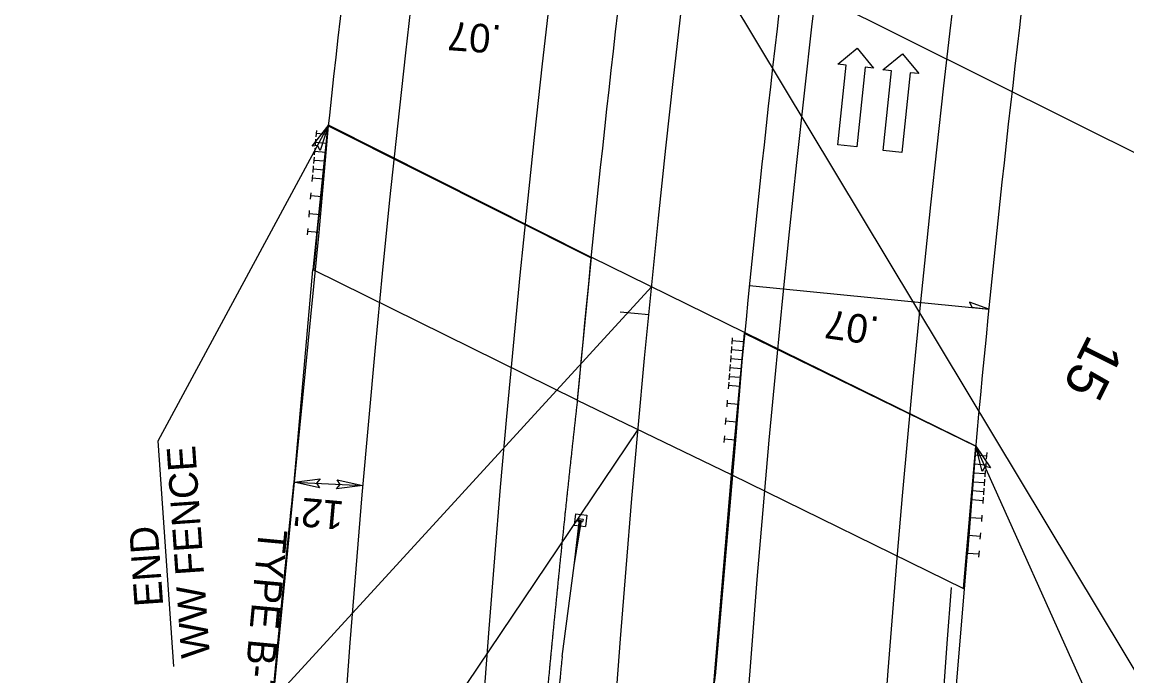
# Model space of a CAD drawing. Extents: x 2389099 to 2405615, y 552200 to 573532.
# Drawn here: x 2400056 to 2400248.8, y 568252.4 to 568366.6 of the extents above; entities that cross this region are included whole.
import ezdxf

# ---------------------------------------------------------------- set-up
doc = ezdxf.new("R2010")
doc.units = 0
for name, color, linetype in [('Prop Approach Slab', 7, 'Continuous'), ('Prop Approach Slab Hatching', 7, 'Continuous'), ('Prop Cable Guiderail Single Face', 7, 'Continuous'), ('Prop Conc Expressway Gutter', 7, 'Continuous'), ('Prop Dimension', 7, 'Continuous'), ('Prop Dimension Text', 7, 'Continuous'), ('Prop DSN Text', 7, 'Continuous'), ('Prop EOT', 7, 'Continuous'), ('Prop Guardrail', 7, 'Continuous'), ('Prop Horizontal Alignment', 7, 'Continuous'), ('Prop Horizontal Alignment Curve and Spiral Data', 7, 'Continuous'), ('Prop Horizontal Alignment Tick Small', 7, 'Continuous'), ('Prop Lane Arrow Through CELL', 7, 'Continuous'), ('Prop SAU III Approach CELL', 7, 'Continuous'), ('Prop Super Arrow 1 Lane CELL', 7, 'Continuous'), ('Prop Superelevation Label', 7, 'Continuous')]:
    doc.layers.add(name, color=color, linetype=linetype)

msp = doc.modelspace()

# ---------------------------------------------------------------- linework, layer by layer
at = {"layer": 'Prop Approach Slab'}
for p, q in [((2400109.42, 568348.51), (2400155.33, 568325.42)), ((2400182.02, 568312.3), (2400222.45, 568292.56))]:
    msp.add_line(p, q, dxfattribs=at)
for radius, start, end in [(2959, 170.18806, 174.3984), (2911, 170.46446, 174.75565), (2883, 170.63278, 174.96393), (2841, 170.90765, 175.29183)]:
    msp.add_arc((2403051.7, 568034.46), radius, start, end, dxfattribs=at)
at = {"layer": 'Prop Approach Slab Hatching'}
for points in [[(2400109.38, 568348.65), (2400155.29, 568325.55), (2400152.89, 568300.54), (2400106.79, 568323.31)], [(2400182.02, 568312.3), (2400179.74, 568287.59), (2400220.29, 568267.65), (2400222.45, 568292.56)]]:
    msp.add_lwpolyline(points, close=True, dxfattribs=at)
at = {"layer": 'Prop Cable Guiderail Single Face'}
msp.add_spline([(2400150.24, 568255.82), (2400150.2, 568255.35), (2400150.11, 568254.45), (2400150.02, 568253.55), (2400149.94, 568252.65), (2400149.85, 568251.75), (2400149.77, 568250.85), (2400149.68, 568249.95), (2400149.6, 568249.05), (2400149.51, 568248.15), (2400149.43, 568247.25), (2400149.35, 568246.35), (2400149.26, 568245.46), (2400149.18, 568244.55), (2400149.1, 568243.65), (2400149.01, 568242.75), (2400148.93, 568241.85), (2400148.85, 568240.95), (2400148.77, 568240.05), (2400148.68, 568239.15), (2400148.6, 568238.25), (2400148.52, 568237.35), (2400148.44, 568236.45), (2400148.36, 568235.55), (2400148.28, 568234.64), (2400148.2, 568233.74)], degree=3, dxfattribs=at)
at = {"layer": 'Prop Conc Expressway Gutter'}
msp.add_lwpolyline([(2400216.81, 568249.06), (2400217.48, 568258.06), (2400218.24, 568267.82)], dxfattribs=at)
at = {"layer": 'Prop Dimension'}
for p, q in [((2400222.45, 568292.56), (2400155.29, 568325.55)), ((2400165.83, 568320.38), (2400033.57, 568175.96)), ((2400152.89, 568300.54), (2400179.74, 568287.59)), ((2400163.47, 568295.43), (2400065.62, 568150.18)), ((2400103.44, 568286.25), (2400115.43, 568285.64))]:
    msp.add_line(p, q, dxfattribs=at)
for points in [[(2400106.6, 568344.92), (2400109.42, 568348.51), (2400107.97, 568344.15), (2400107.54, 568345.04)], [(2400223.59, 568288.14), (2400222.45, 568292.56), (2400225.04, 568288.76), (2400224.07, 568288.96)], [(2400107.89, 568285.24), (2400103.44, 568286.25), (2400108, 568286.82), (2400107.38, 568286.05)], [(2400110.97, 568286.64), (2400115.43, 568285.64), (2400110.87, 568285.07), (2400111.48, 568285.84)]]:
    msp.add_lwpolyline(points, close=True, dxfattribs=at)
at = {"layer": 'Prop DSN Text'}
for p, q in [((2400079.7, 568293.44), (2400109.42, 568348.51)), ((2400082.45, 568254.06), (2400079.7, 568293.44)), ((2400243.18, 568246.41), (2400222.45, 568292.56)), ((2400152.58, 568280.73), (2400152.32, 568278.75)), ((2400152.58, 568280.73), (2400154.56, 568280.47)), ((2400154.56, 568280.47), (2400154.3, 568278.49)), ((2400152.32, 568278.75), (2400154.3, 568278.49)), ((2400152.37, 568271.68), (2400153.25, 568279.64)), ((2400152.37, 568271.68), (2400153.44, 568279.61)), ((2400152.37, 568271.68), (2400153.64, 568279.56)), ((2400153.06, 568279.91), (2400152.99, 568279.42)), ((2400152.99, 568279.42), (2400153.82, 568279.31)), ((2400153.06, 568279.91), (2400153.89, 568279.8)), ((2400153.89, 568279.8), (2400153.82, 568279.31)), ((2400150.24, 568255.82), (2400152.37, 568271.68)), ((2400152.37, 568271.68), (2400152.37, 568271.68))]:
    msp.add_line(p, q, dxfattribs=at)
at = {"layer": 'Prop EOT'}
for p, q in [((2400103.44, 568286.25), (2400106.72, 568323.35)), ((2400176.75, 568251.01), (2400179.81, 568287.55))]:
    msp.add_line(p, q, dxfattribs=at)
for radius, start in [(2923, 119.41161), (2877, 119.41161), (2947, 148.75529), (2853, 154.68245)]:
    msp.add_arc((2403051.7, 568034.46), radius, start, 180.94658, dxfattribs=at)
for points in [[(2400152.89, 568300.53), (2400152.79, 568299.63), (2400152.69, 568298.74), (2400152.59, 568297.84), (2400152.49, 568296.94), (2400152.39, 568296.04), (2400152.29, 568295.13), (2400152.19, 568294.24), (2400152.09, 568293.34), (2400151.99, 568292.44), (2400151.9, 568291.54), (2400151.8, 568290.64), (2400151.7, 568289.74), (2400151.6, 568288.85), (2400151.51, 568287.95), (2400151.41, 568287.05), (2400151.31, 568286.15), (2400151.22, 568285.24), (2400151.12, 568284.34), (2400151.03, 568283.44), (2400150.93, 568282.55), (2400150.84, 568281.65), (2400150.74, 568280.75), (2400150.65, 568279.85), (2400150.55, 568278.95), (2400150.46, 568278.05), (2400150.37, 568277.15), (2400150.27, 568276.25), (2400150.18, 568275.34), (2400150.09, 568274.45), (2400150, 568273.55), (2400149.9, 568272.65), (2400149.81, 568271.75), (2400149.72, 568270.85), (2400149.63, 568269.95), (2400149.54, 568269.05), (2400149.45, 568268.15), (2400149.36, 568267.25), (2400149.27, 568266.35), (2400149.18, 568265.44), (2400149.09, 568264.54), (2400149, 568263.64), (2400148.91, 568262.75), (2400148.82, 568261.85), (2400148.73, 568260.95), (2400148.64, 568260.05), (2400148.56, 568259.15), (2400148.47, 568258.25), (2400148.38, 568257.35), (2400148.29, 568256.45), (2400148.21, 568255.54), (2400148.12, 568254.64), (2400148.03, 568253.74), (2400147.95, 568252.84), (2400147.86, 568251.94), (2400147.78, 568251.04), (2400147.69, 568250.14), (2400147.61, 568249.24), (2400147.52, 568248.34), (2400147.44, 568247.44), (2400147.35, 568246.54), (2400147.27, 568245.64), (2400147.19, 568244.73), (2400147.1, 568243.83), (2400147.02, 568242.93), (2400146.94, 568242.03), (2400146.86, 568241.13), (2400146.77, 568240.23), (2400146.69, 568239.33), (2400146.61, 568238.43), (2400146.53, 568237.53), (2400146.45, 568236.63), (2400146.37, 568235.73), (2400146.29, 568234.82), (2400146.21, 568233.92)], [(2400098.53, 568235.45), (2400098.6, 568236.14), (2400098.66, 568236.82), (2400098.72, 568237.51), (2400098.78, 568238.2), (2400098.84, 568238.89), (2400098.9, 568239.57), (2400098.96, 568240.26), (2400099.02, 568240.95), (2400099.08, 568241.63), (2400099.15, 568242.32), (2400099.21, 568243), (2400099.27, 568243.7), (2400099.33, 568244.38), (2400099.39, 568245.07), (2400099.46, 568245.76), (2400099.52, 568246.44), (2400099.58, 568247.13), (2400099.65, 568247.81), (2400099.71, 568248.5), (2400099.77, 568249.19), (2400099.84, 568249.88), (2400099.9, 568250.56), (2400099.96, 568251.25), (2400100.03, 568251.94), (2400100.09, 568252.62), (2400100.16, 568253.31), (2400100.22, 568253.99), (2400100.29, 568254.68), (2400100.35, 568255.36), (2400100.42, 568256.06), (2400100.48, 568256.75), (2400100.55, 568257.43), (2400100.61, 568258.12), (2400100.68, 568258.8), (2400100.74, 568259.49), (2400100.81, 568260.17), (2400100.88, 568260.86), (2400100.94, 568261.55), (2400101.01, 568262.23), (2400101.08, 568262.92), (2400101.14, 568263.6), (2400101.21, 568264.3), (2400101.28, 568264.98), (2400101.34, 568265.67), (2400101.41, 568266.36), (2400101.48, 568267.04), (2400101.55, 568267.73), (2400101.61, 568268.41), (2400101.68, 568269.1), (2400101.75, 568269.78), (2400101.82, 568270.47), (2400101.89, 568271.16), (2400101.96, 568271.84), (2400102.02, 568272.53), (2400102.09, 568273.21), (2400102.16, 568273.9), (2400102.23, 568274.58), (2400102.3, 568275.27), (2400102.37, 568275.95), (2400102.44, 568276.65), (2400102.51, 568277.34), (2400102.58, 568278.02), (2400102.65, 568278.71), (2400102.72, 568279.39), (2400102.79, 568280.08), (2400102.86, 568280.76), (2400102.93, 568281.45), (2400103.01, 568282.14), (2400103.08, 568282.82), (2400103.15, 568283.51), (2400103.22, 568284.19), (2400103.29, 568284.88), (2400103.44, 568286.25)], [(2400176.95, 568252.4), (2400176.85, 568251.71), (2400176.75, 568251.01), (2400176.65, 568250.32), (2400176.55, 568249.62), (2400176.46, 568248.93), (2400176.36, 568248.24), (2400176.26, 568247.54), (2400176.16, 568246.85), (2400176.06, 568246.16), (2400175.96, 568245.46), (2400175.87, 568244.77), (2400175.77, 568244.07), (2400175.67, 568243.38), (2400175.57, 568242.68), (2400175.48, 568241.98), (2400175.38, 568241.29), (2400175.28, 568240.59), (2400175.19, 568239.9), (2400175.09, 568239.21), (2400174.99, 568238.51), (2400174.9, 568237.82), (2400174.8, 568237.13), (2400174.7, 568236.43), (2400174.61, 568235.73), (2400174.51, 568235.03), (2400174.42, 568234.34), (2400174.32, 568233.65), (2400174.23, 568232.95), (2400174.13, 568232.26), (2400174.04, 568231.57), (2400173.94, 568230.87), (2400173.85, 568230.17), (2400173.75, 568229.47), (2400173.66, 568228.78), (2400173.57, 568228.09), (2400173.47, 568227.39), (2400173.38, 568226.7), (2400173.29, 568225.99), (2400173.19, 568225.3), (2400173.1, 568224.61), (2400173.01, 568223.91), (2400172.91, 568223.22), (2400172.82, 568222.53), (2400172.73, 568221.82), (2400172.64, 568221.13), (2400172.54, 568220.43), (2400172.45, 568219.74), (2400172.36, 568219.05), (2400172.27, 568218.34), (2400172.18, 568217.65), (2400172.09, 568216.95), (2400172, 568216.26), (2400171.9, 568215.57), (2400171.81, 568214.86), (2400171.72, 568214.17), (2400171.63, 568213.48), (2400171.54, 568212.78), (2400171.45, 568212.09), (2400171.36, 568211.38), (2400171.27, 568210.69), (2400171.18, 568210), (2400171.09, 568209.3), (2400171, 568208.6), (2400170.92, 568207.9), (2400170.83, 568207.21), (2400170.74, 568206.52), (2400170.65, 568205.81), (2400170.56, 568205.12), (2400170.47, 568204.43), (2400170.39, 568203.73), (2400170.3, 568203.03), (2400170.21, 568202.33), (2400170.12, 568201.64), (2400170.04, 568200.94)]]:
    msp.add_spline(points, degree=3, dxfattribs=at)
at = {"layer": 'Prop Guardrail'}
for p, q in [((2400107.77, 568329.84), (2400103.44, 568286.25)), ((2400180.52, 568293.61), (2400176.95, 568252.4)), ((2400103.44, 568286.25), (2400098.49, 568234.9)), ((2400218.6, 568244.99), (2400220.99, 568273.87))]:
    msp.add_line(p, q, dxfattribs=at)
msp.add_spline([(2400176.95, 568252.4), (2400176.85, 568251.71), (2400176.75, 568251.01), (2400176.65, 568250.32), (2400176.55, 568249.62), (2400176.46, 568248.93), (2400176.36, 568248.24), (2400176.26, 568247.54), (2400176.16, 568246.85), (2400176.06, 568246.16), (2400175.96, 568245.46), (2400175.87, 568244.77), (2400175.77, 568244.07), (2400175.67, 568243.38), (2400175.57, 568242.68), (2400175.48, 568241.98), (2400175.38, 568241.29), (2400175.28, 568240.59), (2400175.19, 568239.9), (2400175.09, 568239.21), (2400174.99, 568238.51), (2400174.9, 568237.82), (2400174.8, 568237.13), (2400174.7, 568236.43), (2400174.61, 568235.73), (2400174.51, 568235.03), (2400174.42, 568234.34), (2400174.32, 568233.65), (2400174.23, 568232.95), (2400174.13, 568232.26), (2400174.04, 568231.57), (2400173.94, 568230.87), (2400173.85, 568230.17), (2400173.75, 568229.47), (2400173.66, 568228.78), (2400173.57, 568228.09), (2400173.47, 568227.39), (2400173.38, 568226.7), (2400173.29, 568225.99), (2400173.19, 568225.3), (2400173.1, 568224.61), (2400173.01, 568223.91), (2400172.91, 568223.22), (2400172.82, 568222.53), (2400172.73, 568221.82), (2400172.64, 568221.13), (2400172.54, 568220.43), (2400172.45, 568219.74), (2400172.36, 568219.05), (2400172.27, 568218.34), (2400172.18, 568217.65), (2400172.09, 568216.95), (2400172, 568216.26), (2400171.9, 568215.57), (2400171.81, 568214.86), (2400171.72, 568214.17), (2400171.63, 568213.48), (2400171.54, 568212.78), (2400171.45, 568212.09), (2400171.36, 568211.38), (2400171.27, 568210.69), (2400171.18, 568210), (2400171.09, 568209.3), (2400171, 568208.6), (2400170.92, 568207.9), (2400170.83, 568207.21), (2400170.74, 568206.52), (2400170.65, 568205.81), (2400170.56, 568205.12), (2400170.47, 568204.43), (2400170.39, 568203.73), (2400170.3, 568203.03), (2400170.21, 568202.33), (2400170.12, 568201.64), (2400170.04, 568200.94)], degree=3, dxfattribs=at)
at = {"layer": 'Prop Horizontal Alignment'}
msp.add_line((2399810.95, 568562.89), (2400526.85, 568205.84), dxfattribs=at)
msp.add_arc((2403051.7, 568034.46), 2900, 119.41161, 180.94658, dxfattribs=at)
at = {"layer": 'Prop Horizontal Alignment Curve and Spiral Data'}
msp.add_line((2400352.63, 568082.83), (2400172.66, 568382.49), dxfattribs=at)
at = {"layer": 'Prop Horizontal Alignment Tick Small'}
msp.add_line((2400165.35, 568315.46), (2400160.37, 568315.94), dxfattribs=at)
at = {"layer": 'Prop Lane Arrow Through CELL'}
for p, q in [((2400198.35, 568359.23), (2400201.76, 568362.04)), ((2400201.76, 568362.04), (2400204.62, 568358.57)), ((2400206.25, 568358.26), (2400209.66, 568361.07)), ((2400209.66, 568361.07), (2400212.52, 568357.6)), ((2400199.84, 568359.07), (2400198.35, 568359.23)), ((2400198.39, 568345.15), (2400199.84, 568359.07)), ((2400203.12, 568358.73), (2400201.67, 568344.8)), ((2400204.62, 568358.57), (2400203.12, 568358.73)), ((2400207.74, 568358.1), (2400206.25, 568358.26)), ((2400206.29, 568344.18), (2400207.74, 568358.1)), ((2400211.03, 568357.76), (2400209.57, 568343.83)), ((2400212.52, 568357.6), (2400211.03, 568357.76)), ((2400201.67, 568344.8), (2400198.39, 568345.15)), ((2400209.57, 568343.83), (2400206.29, 568344.18))]:
    msp.add_line(p, q, dxfattribs=at)
at = {"layer": 'Prop SAU III Approach CELL'}
for p, q in [((2400109.42, 568348.51), (2400107.77, 568329.84)), ((2400107.2, 568346.15), (2400107.1, 568345.01)), ((2400107.34, 568347.7), (2400107.24, 568346.56)), ((2400109.28, 568346.96), (2400107.29, 568347.13)), ((2400107.06, 568344.59), (2400106.96, 568343.45)), ((2400109, 568343.84), (2400107.01, 568344.02)), ((2400109.14, 568345.4), (2400107.15, 568345.58)), ((2400106.92, 568343.03), (2400106.82, 568341.89)), ((2400108.87, 568342.29), (2400106.87, 568342.46)), ((2400106.79, 568341.48), (2400106.69, 568340.34)), ((2400108.73, 568340.73), (2400106.74, 568340.91)), ((2400106.65, 568339.92), (2400106.55, 568338.78)), ((2400108.59, 568339.17), (2400106.6, 568339.35)), ((2400106.37, 568336.81), (2400106.27, 568335.67)), ((2400108.32, 568336.06), (2400106.32, 568336.24)), ((2400106.1, 568333.7), (2400106, 568332.55)), ((2400108.04, 568332.95), (2400106.05, 568333.12)), ((2400105.82, 568330.58), (2400105.72, 568329.44)), ((2400107.77, 568329.84), (2400105.77, 568330.01)), ((2400179.95, 568311.48), (2400179.86, 568310.33)), ((2400182.02, 568312.3), (2400180.52, 568293.61)), ((2400179.82, 568309.92), (2400179.73, 568308.78)), ((2400181.77, 568309.19), (2400179.78, 568309.35)), ((2400181.9, 568310.74), (2400179.9, 568310.91)), ((2400179.7, 568308.36), (2400179.61, 568307.22)), ((2400181.65, 568307.63), (2400179.65, 568307.79)), ((2400179.57, 568306.8), (2400179.48, 568305.66)), ((2400181.52, 568306.07), (2400179.53, 568306.23)), ((2400179.32, 568303.69), (2400179.23, 568302.55)), ((2400179.45, 568305.25), (2400179.36, 568304.1)), ((2400181.4, 568304.51), (2400179.4, 568304.67)), ((2400181.27, 568302.96), (2400179.28, 568303.12)), ((2400179.07, 568300.57), (2400178.98, 568299.43)), ((2400181.02, 568299.84), (2400179.03, 568300)), ((2400178.82, 568297.46), (2400178.73, 568296.32)), ((2400180.77, 568296.73), (2400178.78, 568296.89)), ((2400178.57, 568294.34), (2400178.48, 568293.2)), ((2400180.52, 568293.61), (2400178.53, 568293.77)), ((2400222.45, 568292.56), (2400220.99, 568273.87)), ((2400222.33, 568291), (2400224.32, 568290.85)), ((2400224.37, 568291.42), (2400224.28, 568290.28)), ((2400222.21, 568289.45), (2400224.2, 568289.29)), ((2400224.12, 568288.3), (2400224.04, 568287.16)), ((2400224.25, 568289.86), (2400224.16, 568288.72)), ((2400221.96, 568286.33), (2400223.96, 568286.17)), ((2400222.09, 568287.89), (2400224.08, 568287.73)), ((2400224, 568286.75), (2400223.91, 568285.6)), ((2400221.84, 568284.77), (2400223.84, 568284.62)), ((2400223.88, 568285.19), (2400223.79, 568284.05)), ((2400221.72, 568283.21), (2400223.72, 568283.06)), ((2400223.76, 568283.63), (2400223.67, 568282.49)), ((2400223.52, 568280.51), (2400223.43, 568279.37)), ((2400221.48, 568280.1), (2400223.47, 568279.94)), ((2400221.23, 568276.98), (2400223.23, 568276.83)), ((2400223.27, 568277.4), (2400223.18, 568276.26)), ((2400220.99, 568273.87), (2400222.98, 568273.71)), ((2400223.03, 568274.28), (2400222.94, 568273.14))]:
    msp.add_line(p, q, dxfattribs=at)
at = {"layer": 'Prop Super Arrow 1 Lane CELL'}
msp.add_line((2400182.93, 568320.62), (2400224.72, 568316.45), dxfattribs=at)
msp.add_lwpolyline([(2400224.72, 568316.45), (2400221.35, 568317.69), (2400221.79, 568316.83)], close=True, dxfattribs=at)

# ---------------------------------------------------------------- texts
at = {"layer": 'Prop Dimension Text'}
for s, rotation, p in [("12'", 174.8377, (2400112.31, 568282.86)), ('TYPE B-77', 264.7043, (2400097.31, 568278.21))]:
    msp.add_text(s, height=5, rotation=rotation, dxfattribs=at).set_placement(p)
at = {"layer": 'Prop DSN Text'}
for s, p in [('WW FENCE', (2400088.75, 568255.7)), ('END ', (2400080.6, 568264.68))]:
    msp.add_text(s, height=5, rotation=93.9999, dxfattribs=at).set_placement(p)
at = {"layer": 'Prop Horizontal Alignment Curve and Spiral Data'}
msp.add_text('15', height=7, rotation=243.4926, dxfattribs=at).set_placement((2400242.22, 568312.28))
at = {"layer": 'Prop Superelevation Label'}
for rotation, p in [(175.7089, (2400139.77, 568366.02)), (171.7321, (2400205.8, 568315.06))]:
    msp.add_text('.07', height=5, rotation=rotation, dxfattribs=at).set_placement(p)

doc.saveas('drawing.dxf')
